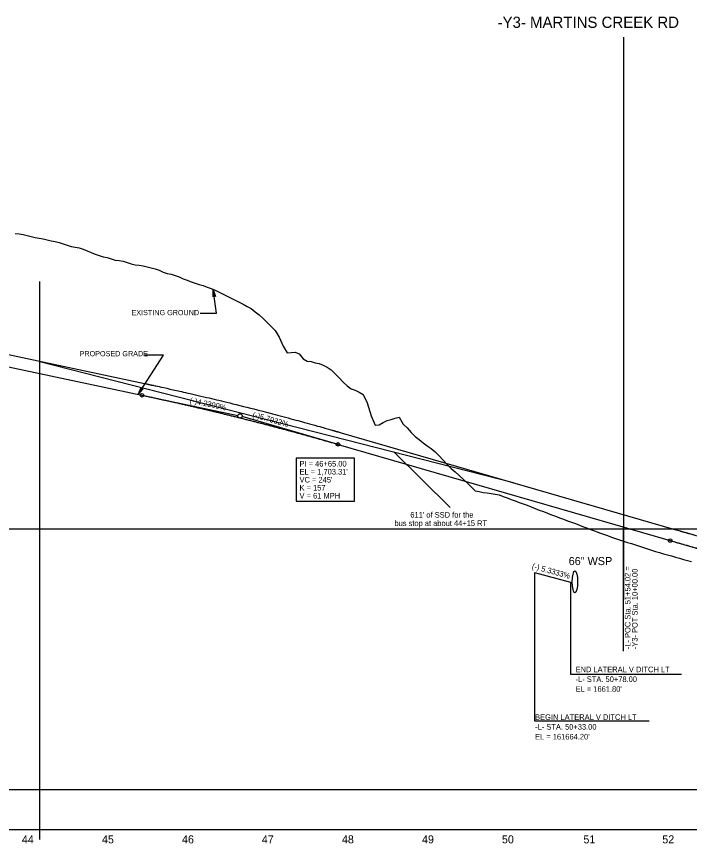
# Model space of a CAD drawing. Extents: x 498575 to 532350, y 405181 to 484585.
# Drawn here: x 509205 to 510046, y 483216 to 484249 of the extents above; entities that cross this region are included whole.
import ezdxf

# ---------------------------------------------------------------- set-up
doc = ezdxf.new("R2010")
doc.units = 0
for name, color, linetype in [('Exist Profile Cell', 7, 'Continuous'), ('Exist Vertical Profile Ground Line', 7, 'Continuous'), ('Exist Vertical Profile Horizontal Axis Label Major', 7, 'Continuous'), ('Prop Drainage Structure Pipe Welded Steel 54in Label', 7, 'Continuous'), ('Prop Grid Mask', 7, 'Continuous'), ('Prop PFL Text', 7, 'Continuous'), ('Prop Vertical Profile Curve Label', 7, 'Continuous'), ('Prop Vertical Profile Ditch Grade Left', 7, 'Continuous'), ('Prop Vertical Profile Ditch Grade Left Label', 7, 'Continuous'), ('Prop Vertical Profile Grade', 7, 'Continuous'), ('Prop Vertical Profile Grade Label', 7, 'Continuous'), ('Prop Vertical Profile Strip Grade', 7, 'Continuous'), ('Prop VPI Label', 7, 'Continuous'), ('Scratch_Level_2', 7, 'Continuous'), ('Scratch_Level_4', 7, 'Continuous'), ('Scratch_Level_5', 7, 'Continuous')]:
    doc.layers.add(name, color=color, linetype=linetype)

msp = doc.modelspace()

# ---------------------------------------------------------------- linework, layer by layer
at = {"layer": 'Exist Profile Cell'}
msp.add_line((505856.7, 483233.7), (526056.7, 483233.7), dxfattribs=at)
at = {"layer": 'Exist Vertical Profile Ground Line'}
for points in [[(509203.2, 483978.4), (509208.2, 483977.8), (509213.2, 483977), (509218.2, 483975.9), (509223.2, 483974.5), (509228.2, 483973.2), (509233.2, 483972.5), (509238.2, 483971.7), (509243.2, 483970.3), (509248.2, 483969.1), (509253.2, 483968.2), (509258.2, 483967), (509263.2, 483965.2), (509268.2, 483963.5), (509273.2, 483962.2), (509278.2, 483961.2), (509283.2, 483960.3), (509288.2, 483958.7), (509293.2, 483956.6), (509298.2, 483954.6), (509303.2, 483952.6), (509308.2, 483950.7), (509313.2, 483949.3)], [(509313.2, 483949.3), (509318.2, 483948.1), (509323.2, 483946.7), (509328.2, 483945.1), (509333.2, 483944.4), (509338.2, 483943.6), (509343.2, 483942), (509348.2, 483940.2), (509353.2, 483939.2), (509358.2, 483938.9), (509363.2, 483938), (509368.2, 483936.5), (509373.2, 483935.2), (509378.2, 483934.1), (509383.2, 483932.3), (509388.2, 483929.9), (509393.2, 483928.1), (509398.2, 483927.4), (509403.2, 483925.8), (509408.2, 483924), (509413.2, 483921.7), (509418.2, 483919.8), (509423.2, 483917.8), (509428.2, 483916.2), (509433.2, 483914.6), (509438.2, 483913.1), (509443.2, 483911.3), (509448.2, 483909.4), (509453.2, 483907.4), (509458.2, 483905.1), (509463.2, 483902.6), (509468.2, 483900), (509473.2, 483897.5), (509478.2, 483894.9), (509483.2, 483892.5), (509488.2, 483889.9), (509493.2, 483887.2), (509498.2, 483884.5), (509503.2, 483880.5), (509508.2, 483876.5), (509513.2, 483871.9), (509518.2, 483867), (509523.2, 483862.1), (509528.2, 483857.1), (509533.2, 483848.7), (509538.2, 483837.6), (509543.2, 483829.3), (509548.2, 483829.7), (509553.2, 483829.8), (509558.2, 483828), (509563.2, 483821.5), (509568.2, 483818.6), (509573.2, 483818.3), (509578.2, 483816.8), (509583.2, 483815.9), (509588.2, 483813.6), (509593.2, 483811.4), (509598.2, 483808), (509603.2, 483802.9), (509608.2, 483797.8), (509613.2, 483792.7), (509618.2, 483788.1), (509623.2, 483784), (509628.2, 483782.5), (509633.2, 483780.1), (509638.2, 483777.1), (509643.2, 483766.7), (509648.2, 483750.5), (509653.2, 483738.9), (509658.2, 483739), (509663.2, 483742.2), (509668.2, 483744.8), (509673.2, 483746), (509678.2, 483747.5), (509683.2, 483748.8), (509688.2, 483739.9), (509693.2, 483735.3), (509698.2, 483729.4), (509703.2, 483724.7), (509708.2, 483720.7), (509713.2, 483716.6), (509718.2, 483712.9), (509723.2, 483709.6), (509728.2, 483705.4), (509733.2, 483700.5), (509738.2, 483695.1), (509743.2, 483689.5), (509748.2, 483684.8), (509753.2, 483680.4), (509758.2, 483675.9), (509763.2, 483671.3), (509768.2, 483666.7), (509773.2, 483661.7), (509778.2, 483656.6), (509783.2, 483655.7), (509788.2, 483654.8), (509793.2, 483654.1), (509798.2, 483653.4), (509803.2, 483652.6), (509808.2, 483651.7), (509813.2, 483649.8)], [(509813.2, 483649.8), (509818.2, 483647.9), (509823.2, 483645.9), (509828.2, 483644.1), (509833.2, 483642.3), (509838.2, 483640.5), (509843.2, 483638.6), (509848.2, 483636.7), (509853.2, 483634.7), (509858.2, 483632.7), (509863.2, 483630.7), (509868.2, 483628.8), (509873.2, 483626.9), (509878.2, 483625), (509883.2, 483623.1), (509888.2, 483621.2), (509893.2, 483619.3), (509898.2, 483617.5), (509903.2, 483615.9), (509908.2, 483613.9), (509913.2, 483611.9), (509918.2, 483610), (509923.2, 483608.1), (509928.2, 483606.2), (509933.2, 483604.4), (509938.2, 483602.5), (509943.2, 483600.7), (509948.2, 483598.9), (509953.2, 483597.2), (509958.2, 483595.5), (509963.2, 483593.9), (509968.2, 483592.2), (509973.2, 483590.7), (509978.2, 483589.1), (509983.2, 483587.5), (509988.2, 483585.9), (509993.2, 483584.2), (509998.2, 483582.6), (510003.2, 483581), (510008.2, 483579.6), (510013.2, 483578.1), (510018.2, 483576.7), (510023.2, 483575.3), (510028.2, 483573.9), (510033.2, 483572.5), (510038.2, 483571.1), (510043.2, 483569.7), (510048.2, 483568.3)]]:
    msp.add_lwpolyline(points, dxfattribs=at)
at = {"layer": 'Prop Drainage Structure Pipe Welded Steel 54in Label'}
msp.add_ellipse((509902.7, 483543), major_axis=(0, 13.8), ratio=0.236364, dxfattribs=at)
at = {"layer": 'Prop Grid Mask'}
msp.add_lwpolyline([(509554.2, 483643.9), (509627.2, 483643.9), (509627.2, 483697.7), (509554.2, 483697.7)], close=True, dxfattribs=at)
at = {"layer": 'Prop PFL Text'}
for p, q in [((509454.8, 483878.8), (509450.7, 483908.4)), ((509434.4, 483878.8), (509454.8, 483878.8)), ((509357, 483777.2), (509388.5, 483826.4)), ((509388.5, 483826.4), (509365.1, 483826.4))]:
    msp.add_line(p, q, dxfattribs=at)
for points in [[(509450.4, 483899.3), (509450.7, 483908.4), (509453.5, 483899.6), (509451.7, 483900.6)], [(509363.1, 483784), (509357, 483777.2), (509360.4, 483785.7), (509361.2, 483783.9)]]:
    msp.add_lwpolyline(points, close=True, dxfattribs=at)
at = {"layer": 'Prop Vertical Profile Curve Label'}
for centre in [(509361.6, 483776.2), (509606.6, 483714.8), (510021.6, 483594.6)]:
    msp.add_circle(centre, 2.25, dxfattribs=at)
at = {"layer": 'Prop Vertical Profile Ditch Grade Left'}
msp.add_lwpolyline([(509852.1, 483554.7), (509897.1, 483542.7), (509897.1, 483542.7)], dxfattribs=at)
at = {"layer": 'Prop Vertical Profile Ditch Grade Left Label'}
for p, q in [((509852.1, 483554.7), (509852.1, 483369.2)), ((509897.1, 483542.7), (509897.1, 483427.6)), ((509897.1, 483427.6), (510035.8, 483427.6)), ((509852.1, 483369.2), (509995.5, 483369.2))]:
    msp.add_line(p, q, dxfattribs=at)
at = {"layer": 'Prop Vertical Profile Grade'}
for p, q in [((508596.6, 483938), (509361.6, 483776.2)), ((509606.6, 483714.8), (510021.6, 483594.6))]:
    msp.add_line(p, q, dxfattribs=at)
for points in [[(509361.6, 483776.2), (509366.5, 483775.2), (509371.4, 483774.1), (509376.3, 483773.1), (509381.2, 483772), (509386.1, 483770.9), (509391, 483769.8), (509395.9, 483768.8), (509400.8, 483767.7), (509405.7, 483766.6), (509410.6, 483765.4), (509415.5, 483764.3), (509420.4, 483763.2), (509425.3, 483762.1), (509430.2, 483760.9), (509435.1, 483759.8), (509440, 483758.6), (509444.9, 483757.5), (509449.8, 483756.3), (509454.7, 483755.1), (509459.6, 483753.9), (509464.5, 483752.7), (509469.4, 483751.5), (509474.3, 483750.3), (509479.2, 483749.1), (509484.1, 483747.9), (509489, 483746.7), (509493.9, 483745.4), (509498.8, 483744.2), (509503.7, 483742.9), (509508.6, 483741.7), (509513.5, 483740.4), (509518.4, 483739.1), (509523.3, 483737.8), (509528.2, 483736.5), (509533.1, 483735.2), (509538, 483733.9), (509542.9, 483732.6), (509547.8, 483731.3), (509552.7, 483730), (509557.6, 483728.6), (509562.5, 483727.3), (509567.4, 483725.9), (509572.3, 483724.6), (509577.2, 483723.2), (509582.1, 483721.8), (509587, 483720.4), (509591.9, 483719), (509596.8, 483717.6), (509601.7, 483716.2), (509606.6, 483714.8)], [(510021.6, 483594.6), (510030.9, 483591.9), (510040.2, 483589.3), (510049.5, 483586.7), (510058.8, 483584.1), (510068.1, 483581.6), (510077.4, 483579.1), (510086.7, 483576.6), (510096, 483574.2), (510105.3, 483571.8), (510114.6, 483569.5), (510123.9, 483567.2), (510133.2, 483564.9), (510142.5, 483562.7), (510151.8, 483560.5), (510161.1, 483558.3), (510170.4, 483556.2), (510179.7, 483554.1), (510189, 483552), (510198.3, 483550), (510207.6, 483548), (510216.9, 483546.1), (510226.2, 483544.2), (510235.5, 483542.3), (510244.8, 483540.4), (510254.1, 483538.6), (510263.4, 483536.9), (510272.7, 483535.1), (510282, 483533.5), (510291.3, 483531.8), (510300.6, 483530.2), (510309.9, 483528.6), (510319.2, 483527.1), (510328.5, 483525.5), (510337.8, 483524.1), (510347.1, 483522.6), (510356.4, 483521.2), (510365.7, 483519.9), (510375, 483518.6), (510384.3, 483517.3), (510393.6, 483516), (510402.9, 483514.8), (510412.2, 483513.6), (510421.5, 483512.5), (510430.8, 483511.4), (510440.1, 483510.3), (510449.4, 483509.3), (510458.7, 483508.3), (510468, 483507.3), (510477.3, 483506.4), (510486.6, 483505.5)]]:
    msp.add_spline(points, degree=3, dxfattribs=at)
at = {"layer": 'Prop Vertical Profile Strip Grade'}
msp.add_line((509963.5, 483456.3), (509963.5, 483611.4), dxfattribs=at)
at = {"layer": 'Prop VPI Label'}
for p, q in [((509361.6, 483776.2), (509481.4, 483750.9)), ((509606.6, 483714.8), (509486.7, 483749.5)), ((510021.6, 483594.6), (510251.4, 483528))]:
    msp.add_line(p, q, dxfattribs=at)
msp.add_circle((509484.1, 483750.3), 2.75, dxfattribs=at)
at = {"layer": 'Scratch_Level_2'}
msp.add_line((509963.5, 484223.4), (509963.5, 483520.5), dxfattribs=at)
at = {"layer": 'Scratch_Level_4'}
msp.add_line((505856.7, 483283.7), (512195.1, 483283.7), dxfattribs=at)
at = {"layer": 'Scratch_Level_5'}
for p, q in [((508599.7, 483952.7), (509364.7, 483790.9)), ((509234.1, 483221.2), (509234.1, 483918.2)), ((509234.1, 483818.5), (509826, 483667.1)), ((509610.7, 483729.2), (510025.7, 483609)), ((509746.8, 483636), (509676.4, 483705.4)), ((513582.6, 483609), (498575.1, 483609))]:
    msp.add_line(p, q, dxfattribs=at)
for points in [[(509364.7, 483790.9), (509366, 483790.6), (509367.6, 483790.3), (509369.2, 483789.9), (509369.6, 483789.8), (509369.6, 483789.8), (509369.6, 483789.8), (509369.7, 483789.8), (509369.8, 483789.8), (509370.1, 483789.7), (509370.3, 483789.7), (509371.1, 483789.5), (509372.4, 483789.2), (509373.7, 483788.9), (509374.4, 483788.8), (509374.5, 483788.8), (509374.5, 483788.8), (509374.6, 483788.8), (509374.7, 483788.7), (509374.9, 483788.7), (509375.5, 483788.6), (509377.3, 483788.2), (509384.1, 483786.7), (509400.8, 483783), (509416.3, 483779.5), (509447.2, 483772.4), (509467.8, 483767.4), (509508.8, 483757.2), (509529.3, 483751.8), (509559.9, 483743.6), (509570.1, 483740.7), (509585.3, 483736.5), (509591.7, 483734.7), (509598.4, 483732.8), (509600.1, 483732.3), (509600.6, 483732.1), (509600.8, 483732.1), (509600.9, 483732), (509600.9, 483732), (509601.1, 483732), (509601.8, 483731.8), (509603.1, 483731.4), (509604.4, 483731), (509605.2, 483730.8), (509605.4, 483730.7), (509605.7, 483730.7), (509605.8, 483730.6), (509605.8, 483730.6), (509605.8, 483730.6), (509605.9, 483730.6), (509605.9, 483730.6), (509606.3, 483730.5), (509607.9, 483730), (509609.5, 483729.6), (509610.7, 483729.2)], [(510025.7, 483609), (510028.1, 483608.3), (510031.1, 483607.5), (510034.1, 483606.6), (510034.8, 483606.4), (510034.9, 483606.4), (510035, 483606.3), (510035, 483606.3), (510035, 483606.3), (510035.2, 483606.3), (510035.7, 483606.2), (510036.1, 483606), (510037.6, 483605.6), (510038.7, 483605.3), (510041.1, 483604.6), (510042.3, 483604.3), (510043.6, 483603.9), (510043.8, 483603.9), (510044, 483603.8), (510044.2, 483603.7), (510044.6, 483603.6), (510045.5, 483603.4), (510048.8, 483602.4), (510051.7, 483601.6), (510058.8, 483599.6), (510063.6, 483598.3), (510073, 483595.8), (510077.8, 483594.5), (510092, 483590.7), (510101.5, 483588.2), (510120.6, 483583.4), (510130.1, 483581.1), (510158.8, 483574.1), (510177.9, 483569.8), (510206.7, 483563.5), (510216.3, 483561.5), (510235.5, 483557.5), (510245.2, 483555.6), (510274.1, 483550.1), (510293.4, 483546.6), (510332.2, 483540.1), (510351.6, 483537.1), (510380.7, 483532.9), (510390.4, 483531.5), (510409.9, 483529), (510419.7, 483527.8), (510439.2, 483525.5), (510448.9, 483524.4), (510461.1, 483523.1), (510464.2, 483522.8), (510467.5, 483522.4), (510468.6, 483522.3), (510469.1, 483522.3), (510469.4, 483522.2), (510469.5, 483522.2), (510469.5, 483522.2), (510469.5, 483522.2), (510469.6, 483522.2), (510470.8, 483522.1), (510472.1, 483521.9), (510474.5, 483521.7), (510475.8, 483521.6), (510477.3, 483521.4), (510477.6, 483521.4), (510478, 483521.4), (510478.3, 483521.3), (510478.5, 483521.3), (510478.6, 483521.3), (510478.7, 483521.3), (510478.7, 483521.3), (510478.7, 483521.3), (510478.7, 483521.3), (510479.4, 483521.2), (510482.5, 483520.9), (510485.5, 483520.6), (510488, 483520.4)]]:
    msp.add_open_spline(points, degree=3, dxfattribs=at)

# ---------------------------------------------------------------- texts
at = {"layer": 'Exist Vertical Profile Horizontal Axis Label Major'}
for s, p in [('44', (509211.5, 483216.2)), ('44', (509211.5, 483216.2)), ('45', (509311.6, 483216.2)), ('45', (509311.6, 483216.2)), ('46', (509411.6, 483216.2)), ('46', (509411.6, 483216.2)), ('47', (509511.4, 483216.2)), ('47', (509511.4, 483216.2)), ('48', (509611.5, 483216.2)), ('48', (509611.5, 483216.2)), ('49', (509711.6, 483216.2)), ('49', (509711.6, 483216.2)), ('50', (509811.5, 483216.2)), ('50', (509811.5, 483216.2)), ('51', (509913.3, 483216.2)), ('51', (509913.3, 483216.2)), ('52', (510011.9, 483216.2)), ('52', (510011.9, 483216.2))]:
    msp.add_text(s, height=10, dxfattribs=at).set_placement(p)
at = {"layer": 'Prop Drainage Structure Pipe Welded Steel 54in Label'}
msp.add_text('66" WSP', height=10.12, dxfattribs=at).set_placement((509894.9, 483563.9))
at = {"layer": 'Prop PFL Text'}
for s, p in [('EXISTING GROUND', (509348.5, 483876.2)), ('PROPOSED GRADE', (509283.6, 483824.9))]:
    msp.add_text(s, height=6.516, dxfattribs=at).set_placement(p)
at = {"layer": 'Prop Vertical Profile Curve Label'}
for s, p in [("VC = 245'", (509558.5, 483667.1)), ('K = 157', (509558.5, 483657.1)), ('V = 61 MPH ', (509558.5, 483647.1))]:
    msp.add_text(s, height=7, dxfattribs=at).set_placement(p)
at = {"layer": 'Prop Vertical Profile Ditch Grade Left Label'}
for s, rotation, p in [('(-) 5.3333%', 344.6236, (509848.4, 483559.7)), ('END LATERAL V DITCH LT', 360, (509903.5, 483430.1)), ('-L- STA. 50+78.00', 360, (509903.5, 483417.8)), ("EL = 1661.80'", 360, (509903.5, 483405.6)), ('BEGIN LATERAL V DITCH LT', 360, (509852.9, 483370.5)), ('-L- STA. 50+33.00', 360, (509852.9, 483358.3)), ("EL = 161664.20'", 360, (509852.9, 483346))]:
    msp.add_text(s, height=7, rotation=rotation, dxfattribs=at).set_placement(p)
at = {"layer": 'Prop Vertical Profile Grade Label'}
for s, rotation, p in [('(-)4.2300%', 348.0579, (509420.8, 483766.7)), ('(-)5.7932%', 343.8458, (509499.1, 483749))]:
    msp.add_text(s, height=7, rotation=rotation, dxfattribs=at).set_placement(p)
at = {"layer": 'Prop Vertical Profile Strip Grade'}
for s, p in [('-L- POC Sta. 51+54.02 = ', (509972.1, 483458.8)), ('-Y3- POT Sta. 10+00.00', (509981, 483458.8))]:
    msp.add_text(s, height=7, rotation=90, dxfattribs=at).set_placement(p)
at = {"layer": 'Prop VPI Label'}
for s, p in [('PI = 46+65.00', (509558.5, 483687.1)), ("EL = 1,703.31'", (509558.5, 483677.1))]:
    msp.add_text(s, height=7, dxfattribs=at).set_placement(p)
at = {"layer": 'Scratch_Level_2'}
msp.add_text('-Y3- MARTINS CREEK RD', height=14, dxfattribs=at).set_placement((509806, 484235.2))
at = {"layer": 'Scratch_Level_5'}
for s, p in [("611' of SSD for the", (509697, 483623.2)), ('bus stop at about 44+15 RT', (509677.1, 483612.7))]:
    msp.add_text(s, height=7, dxfattribs=at).set_placement(p)

doc.saveas('drawing.dxf')
